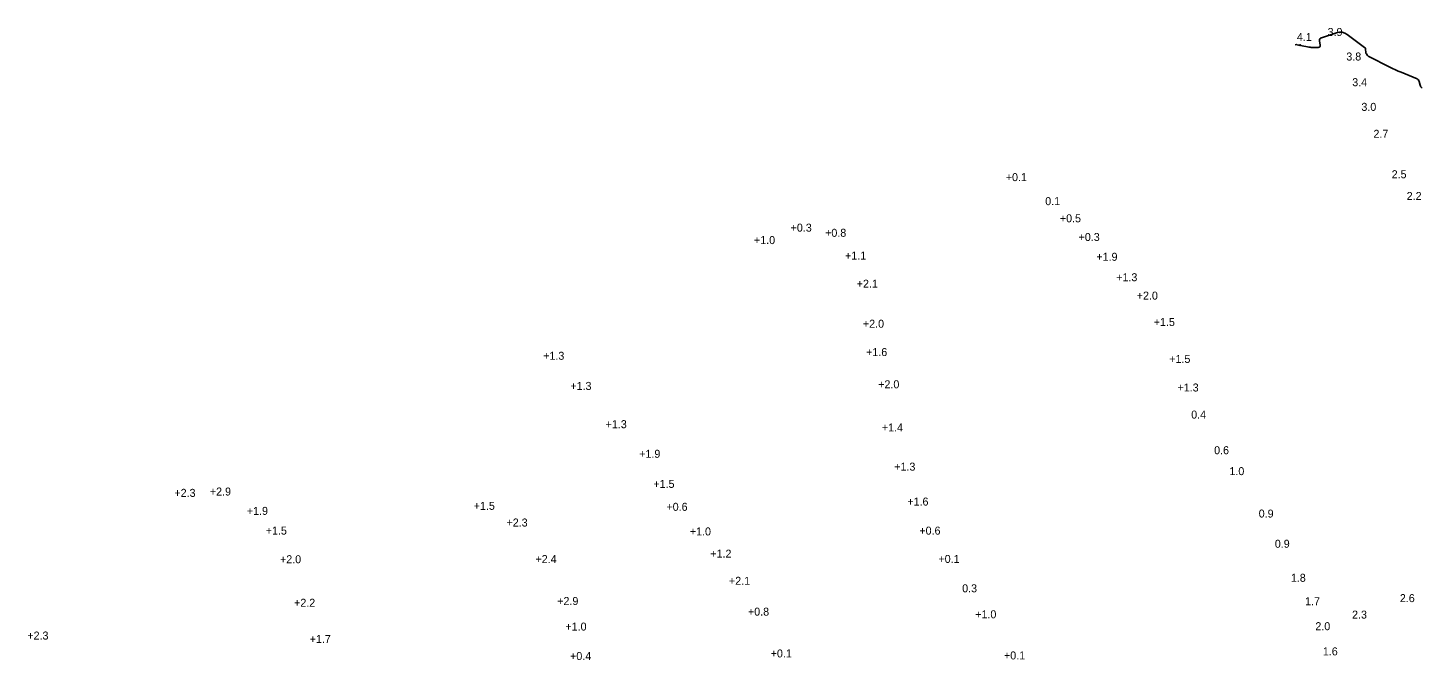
# Model space of a CAD drawing. Extents: x 837127 to 848654, y 3074248 to 3079868.
# Drawn here: x 847289 to 847833, y 3078716 to 3078963 of the extents above; entities that cross this region are included whole.
import ezdxf

# ---------------------------------------------------------------- set-up
doc = ezdxf.new("R2010")
doc.units = 0
doc.layers.add('V-HYDS-MAJR', color=7, linetype='Continuous')
doc.layers.add('V-HYDS-SOUN', color=7, linetype='Continuous')

msp = doc.modelspace()

# ---------------------------------------------------------------- linework, layer by layer
at = {"layer": 'V-HYDS-MAJR'}
msp.add_lwpolyline([(847783.28, 3078956.08), (847783.9, 3078956.22), (847783.94, 3078956.22), (847783.98, 3078956.21), (847784.01, 3078956.19), (847784.04, 3078956.16), (847784.13, 3078956.01), (847784.15, 3078955.98), (847784.18, 3078955.96), (847784.22, 3078955.95), (847784.26, 3078955.95), (847784.61, 3078955.99), (847784.64, 3078955.99), (847784.66, 3078955.98), (847784.68, 3078955.97), (847784.69, 3078955.94), (847784.73, 3078955.82), (847784.75, 3078955.8), (847784.76, 3078955.79), (847784.78, 3078955.78), (847784.81, 3078955.79), (847785.3, 3078956.07), (847785.33, 3078956.08), (847785.35, 3078956.08), (847785.37, 3078956.06), (847785.37, 3078956.03), (847785.37, 3078955.88), (847785.38, 3078955.84), (847785.39, 3078955.82), (847785.41, 3078955.8), (847785.45, 3078955.79), (847788.75, 3078955.1), (847788.85, 3078955.08), (847788.95, 3078955.06), (847789.05, 3078955.05), (847789.15, 3078955.05), (847789.56, 3078955.02), (847789.66, 3078955.02), (847789.76, 3078955.02), (847789.86, 3078955.01), (847789.97, 3078955.01), (847792.32, 3078955), (847792.68, 3078955.05), (847792.93, 3078955.21), (847793.06, 3078955.47), (847793.08, 3078955.84), (847792.88, 3078957.63), (847792.89, 3078958.04), (847793.02, 3078958.36), (847793.26, 3078958.62), (847793.63, 3078958.79), (847799.51, 3078960.74), (847800.61, 3078960.97), (847801.67, 3078960.94), (847802.68, 3078960.64), (847803.65, 3078960.06), (847810.44, 3078954.96), (847810.61, 3078954.81), (847810.73, 3078954.63), (847810.81, 3078954.43), (847810.84, 3078954.2), (847810.9, 3078953.13), (847810.92, 3078952.96), (847810.97, 3078952.79), (847811.04, 3078952.63), (847811.13, 3078952.48), (847811.54, 3078951.89), (847811.65, 3078951.75), (847811.77, 3078951.63), (847811.91, 3078951.53), (847812.06, 3078951.44), (847820.23, 3078947.36), (847821.35, 3078946.81), (847822.47, 3078946.28), (847823.61, 3078945.77), (847824.75, 3078945.28), (847830.94, 3078942.69), (847831.25, 3078942.51), (847831.5, 3078942.29), (847831.68, 3078942.01), (847831.8, 3078941.67), (847832.14, 3078940.22), (847832.25, 3078939.87), (847832.42, 3078939.57), (847832.64, 3078939.29), (847832.92, 3078939.06)], dxfattribs=at)

# ---------------------------------------------------------------- texts
at = {"layer": 'V-HYDS-SOUN'}
for s, p in [('4.1', (847784, 3078957.54)), ('3.9', (847796, 3078959.49)), ('3.8', (847803.31, 3078949.9)), ('3.4', (847805.62, 3078939.86)), ('3.0', (847809.19, 3078930.22)), ('2.7', (847813.91, 3078919.7)), ('+0.1 ', (847670.34, 3078902.76)), ('2.5', (847821.01, 3078903.89)), ('2.2', (847826.87, 3078895.4)), ('0.1', (847685.74, 3078893.37)), ('+0.5 ', (847691.46, 3078886.67)), ('+1.0 ', (847572.02, 3078878.16)), ('+0.3 ', (847586.33, 3078883.02)), ('+0.8 ', (847599.8, 3078881.01)), ('+0.3 ', (847698.77, 3078879.37)), ('+1.1 ', (847607.58, 3078872.07)), ('+1.9 ', (847705.71, 3078871.63)), ('+1.3 ', (847713.47, 3078863.64)), ('+2.1 ', (847612.15, 3078861.11)), ('+2.0 ', (847721.48, 3078856.45)), ('+2.0 ', (847614.56, 3078845.46)), ('+1.5 ', (847728.12, 3078846.13)), ('+1.3 ', (847489.72, 3078832.94)), ('+1.6 ', (847615.8, 3078834.39)), ('+1.5 ', (847734.17, 3078831.71)), ('+1.3 ', (847500.33, 3078821.15)), ('+2.0 ', (847620.53, 3078821.79)), ('+1.3 ', (847737.39, 3078820.54)), ('0.4', (847742.74, 3078809.96)), ('+1.3 ', (847514.1, 3078806.2)), ('+1.4 ', (847621.96, 3078804.92)), ('+1.9 ', (847527.21, 3078794.63)), ('0.6', (847751.69, 3078796.02)), ('+1.3 ', (847626.79, 3078789.61)), ('1.0', (847757.66, 3078787.85)), ('+1.5 ', (847532.75, 3078782.87)), ('+2.3 ', (847345.73, 3078779.36)), ('+2.9 ', (847359.57, 3078779.88)), ('+1.6 ', (847631.9, 3078775.95)), ('+1.9 ', (847374.01, 3078772.32)), ('+1.5 ', (847462.59, 3078774.29)), ('+0.6 ', (847537.85, 3078773.91)), ('0.9', (847769.1, 3078771.27)), ('+1.5 ', (847381.4, 3078764.61)), ('+2.3 ', (847475.4, 3078767.77)), ('+1.0 ', (847546.98, 3078764.29)), ('+0.6 ', (847636.6, 3078764.6)), ('0.9', (847775.39, 3078759.47)), ('+2.0 ', (847386.96, 3078753.42)), ('+2.4 ', (847486.7, 3078753.48)), ('+1.2 ', (847554.97, 3078755.59)), ('+0.1 ', (847644.05, 3078753.54)), ('+2.1 ', (847562.26, 3078744.98)), ('0.3', (847653.31, 3078742.06)), ('1.8', (847781.66, 3078746.17)), ('+2.9 ', (847495.21, 3078737.08)), ('1.7', (847787.22, 3078737.02)), ('2.6', (847824.21, 3078738.22)), ('+2.2 ', (847392.46, 3078736.41)), ('+0.8 ', (847569.68, 3078732.94)), ('+1.0 ', (847658.41, 3078731.9)), ('2.3', (847805.55, 3078731.78)), ('+1.0 ', (847498.4, 3078727.1)), ('2.0', (847791.22, 3078727.25)), ('+2.3 ', (847288.31, 3078723.59)), ('+1.7 ', (847398.54, 3078722.26)), ('+0.4 ', (847500.22, 3078715.59)), ('+0.1 ', (847578.55, 3078716.6)), ('+0.1 ', (847669.64, 3078715.82)), ('1.6', (847794.14, 3078717.41))]:
    msp.add_text(s, height=3.125, dxfattribs=at).set_placement(p)

doc.saveas('drawing.dxf')
